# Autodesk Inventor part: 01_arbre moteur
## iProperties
Shininess: 20.0
Length Units: 11270
Angle Units: 11279
Time Units: 11290
Mass Units: 11283
Length Display Precision: 3
Angle Display Precision: 2
Created: 2000-10
Part Number: 01_arbre moteur
Material: Par défaut
Document SubType Name: Modélisation
Density: 1.0
Volumn: 87.55514191337089
Area: 187.97380756929144
PropertySet Name: Model Information
Control State: 0
Master: False
Checked Out: False
Author: Laurent GAUTHERON
